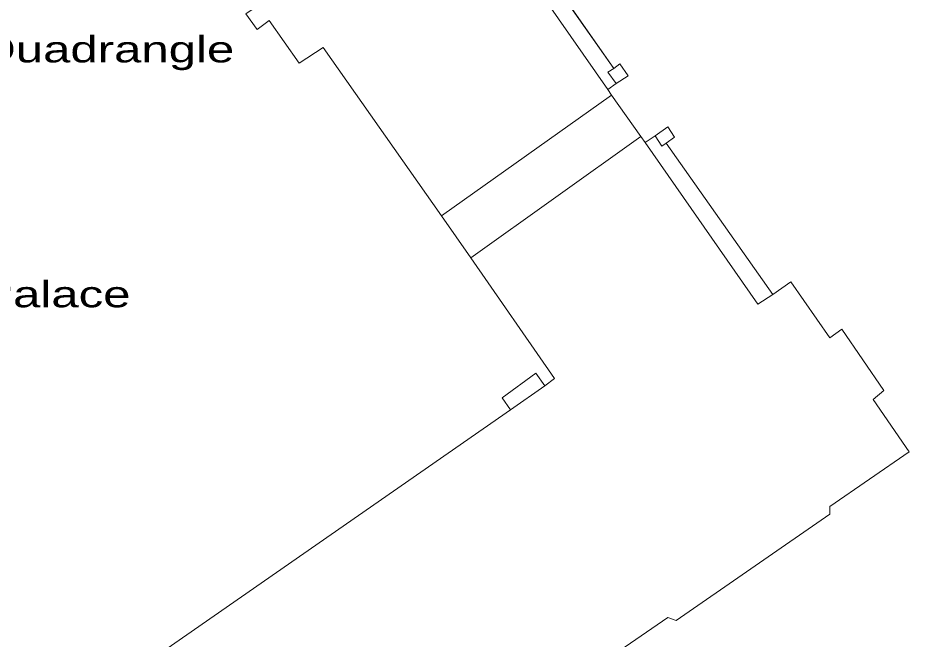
# Model space of a CAD drawing. Extents: x 528790 to 529292, y 179350 to 179856.
# Drawn here: x 529045.4 to 529104.9, y 179626.8 to 179668.3 of the extents above; entities that cross this region are included whole.
import ezdxf

# ---------------------------------------------------------------- set-up
doc = ezdxf.new("R2010")
doc.units = 0
doc.header["$LTSCALE"] = 0.6
doc.layers.add('1', color=7, linetype='Continuous', lineweight=13)
doc.layers.add('2', color=7, linetype='Continuous', lineweight=13)
doc.layers.add('5', color=7, linetype='Continuous')

msp = doc.modelspace()

# ---------------------------------------------------------------- linework, layer by layer
at = {"layer": '1'}
for points in [[(529084.8, 179663.5), (529077.55, 179673.9), (529078.45, 179674.55), (529080.05, 179675.7), (529077.1, 179680), (529074, 179677.9), (529074.4, 179677.4), (529064, 179670.3), (529063.6, 179670.55), (529060.65, 179668.55), (529061.4, 179667.5), (529062.2, 179668.1), (529064.2, 179665.25), (529065.8, 179666.3), (529073.7, 179655.05), (529085.05, 179663.1)], [(529078.45, 179674.55), (529077.55, 179673.9), (529084.8, 179663.5), (529085.35, 179663.9), (529084.8, 179664.65), (529085.2, 179664.9)], [(529085.2, 179664.9), (529084.8, 179664.65), (529085.35, 179663.9), (529086.15, 179664.4), (529085.6, 179665.2)], [(529085.05, 179663.1), (529073.7, 179655.05), (529075.65, 179652.25), (529087, 179660.35)], [(529088.7, 179659.9), (529089.25, 179660.3), (529088.8, 179661), (529087.95, 179660.4), (529088.4, 179659.7)], [(529088.7, 179659.9), (529088.4, 179659.7), (529087.95, 179660.4), (529087.28, 179659.95), (529094.8, 179649.15), (529095.8, 179649.8)], [(529078.3, 179642.1), (529080.6, 179643.7), (529080, 179644.55), (529077.75, 179642.9)]]:
    msp.add_lwpolyline(points, close=True, dxfattribs=at)
for points in [[(529078.45, 179674.55), (529085.2, 179664.9), (529085.6, 179665.2), (529086.15, 179664.4), (529085.35, 179663.9), (529084.8, 179663.5), (529085.05, 179663.1), (529087, 179660.35), (529087.28, 179659.95), (529087.95, 179660.4), (529088.8, 179661), (529089.25, 179660.3), (529088.7, 179659.9), (529095.8, 179649.8), (529097, 179650.65), (529099.6, 179646.9), (529100.4, 179647.5), (529103.2, 179643.4), (529102.5, 179642.8), (529104.9, 179639.3), (529099.6, 179635.65), (529099.6, 179635.15), (529089.35, 179628.05), (529088.8, 179628.25), (529085.25, 179625.8)], [(529030, 179608.3), (529047, 179620.15), (529046.35, 179621.1), (529047.65, 179622), (529046.4, 179623.75), (529049.2, 179625.7), (529050.5, 179623.95), (529052, 179625), (529052.55, 179624.2), (529078.3, 179642.1), (529077.75, 179642.9), (529080, 179644.55), (529080.6, 179643.7), (529081.25, 179644.2), (529075.65, 179652.25), (529073.7, 179655.05), (529065.8, 179666.3), (529064.2, 179665.25), (529062.2, 179668.1), (529061.4, 179667.5), (529060.65, 179668.55)], [(529085.25, 179625.8), (529088.8, 179628.25), (529089.35, 179628.05), (529099.6, 179635.15), (529099.6, 179635.65), (529104.9, 179639.3), (529102.5, 179642.8), (529103.2, 179643.4), (529100.4, 179647.5), (529099.6, 179646.9), (529097, 179650.65), (529095.8, 179649.8), (529094.8, 179649.15), (529087.28, 179659.95), (529087, 179660.35), (529075.65, 179652.25), (529081.25, 179644.2), (529080.6, 179643.7), (529078.3, 179642.1), (529052.55, 179624.2)]]:
    msp.add_lwpolyline(points, dxfattribs=at)
at = {"layer": '2'}
for p, q in [((529078.45, 179674.55), (529085.2, 179664.9)), ((529085.35, 179663.9), (529084.8, 179663.5)), ((529073.7, 179655.05), (529085.05, 179663.1)), ((529084.8, 179663.5), (529085.05, 179663.1)), ((529085.05, 179663.1), (529087, 179660.35)), ((529075.65, 179652.25), (529087, 179660.35)), ((529087, 179660.35), (529087.28, 179659.95)), ((529087.95, 179660.4), (529087.28, 179659.95)), ((529095.8, 179649.8), (529088.7, 179659.9)), ((529075.65, 179652.25), (529073.7, 179655.05)), ((529078.3, 179642.1), (529080.6, 179643.7))]:
    msp.add_line(p, q, dxfattribs=at)
for points in [[(529078.45, 179674.55), (529077.55, 179673.9), (529084.8, 179663.5)], [(529073.7, 179655.05), (529065.8, 179666.3), (529064.2, 179665.25), (529062.2, 179668.1), (529061.4, 179667.5), (529060.65, 179668.55)], [(529085.35, 179663.9), (529084.8, 179664.65), (529085.2, 179664.9)], [(529085.2, 179664.9), (529085.6, 179665.2), (529086.15, 179664.4), (529085.35, 179663.9)], [(529087.95, 179660.4), (529088.8, 179661), (529089.25, 179660.3), (529088.7, 179659.9)], [(529088.7, 179659.9), (529088.4, 179659.7), (529087.95, 179660.4)], [(529087.28, 179659.95), (529094.8, 179649.15), (529095.8, 179649.8)], [(529080.6, 179643.7), (529081.25, 179644.2), (529075.65, 179652.25)], [(529095.8, 179649.8), (529097, 179650.65), (529099.6, 179646.9), (529100.4, 179647.5), (529103.2, 179643.4), (529102.5, 179642.8), (529104.9, 179639.3), (529099.6, 179635.65), (529099.6, 179635.15), (529089.35, 179628.05), (529088.8, 179628.25), (529085.25, 179625.8), (529086.5, 179624.15)], [(529078.3, 179642.1), (529077.75, 179642.9), (529080, 179644.55), (529080.6, 179643.7)], [(529050.5, 179623.95), (529052, 179625), (529052.55, 179624.2), (529078.3, 179642.1)]]:
    msp.add_lwpolyline(points, dxfattribs=at)

# ---------------------------------------------------------------- texts
at = {"layer": '5', "width": 1.4}
for s, p in [('The Quadrangle', (529036.2, 179665.3)), ('Buckingham Palace', (529024, 179648.95))]:
    msp.add_text(s, height=1.75, dxfattribs=at).set_placement(p)

doc.saveas('drawing.dxf')
